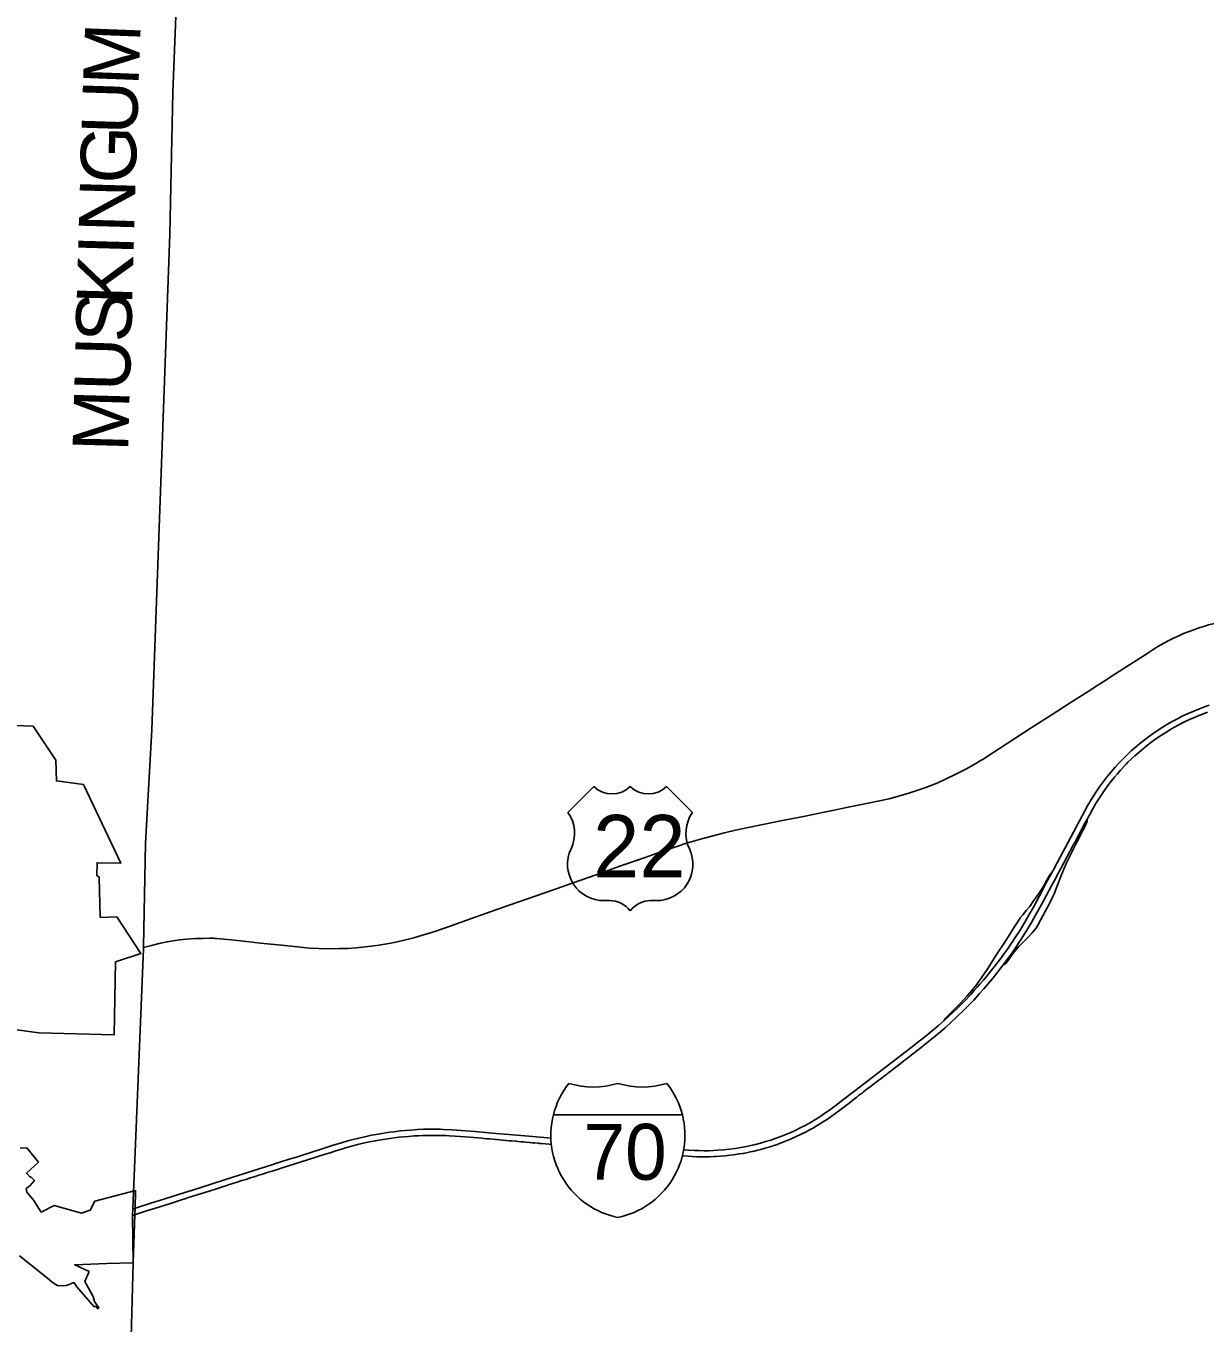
# Model space of a CAD drawing. Extents: x 1913970 to 2397567, y 78841 to 829347.
# Drawn here: x 2183521 to 2204756, y 720753 to 744108 of the extents above; entities that cross this region are included whole.
import ezdxf

# ---------------------------------------------------------------- set-up
doc = ezdxf.new("R2010")
doc.units = 0
for name, color, linetype in [('GM_X_Corporation', 7, 'Continuous'), ('GM_X_County', 7, 'Continuous'), ('GM_X_County_Text', 7, 'Continuous'), ('GM_X_Interstate_Location', 7, 'Continuous'), ('GM_X_Interstate_Shield', 7, 'Continuous'), ('GM_X_US_Location', 7, 'Continuous'), ('GM_X_US_Route', 7, 'Continuous'), ('GM_X_US_Shield', 7, 'Continuous'), ('UT_P_Electric', 7, 'Continuous')]:
    doc.layers.add(name, color=color, linetype=linetype)

msp = doc.modelspace()

# ---------------------------------------------------------------- linework, layer by layer
at = {"layer": 'GM_X_Corporation'}
for points in [[(2182981, 731524), (2183650, 731502), (2184058, 730889), (2184071, 730515), (2184559, 730451), (2185232, 729036), (2184802, 729041), (2184800, 728810), (2184842, 728783), (2184858, 728058), (2185156, 728065), (2185589, 727405), (2185132, 727255), (2185107, 725943), (2183756, 725981), (2182382, 726167)], [(2183418, 723904), (2183538, 723905), (2183746, 723650), (2183529, 723453), (2183600, 723377), (2183608, 723386), (2183673, 723319), (2183591, 723223), (2183523, 723174), (2183537, 723107), (2183663, 722957), (2183797, 722750), (2184031, 722868), (2184520, 722733), (2184678, 722787), (2184759, 722946), (2185491, 723138), (2185486, 722822), (2185483, 722707), (2185450, 721840), (2184976, 721823), (2184399, 721803), (2184659, 721681), (2184581, 721503), (2184730, 721231), (2184758, 721140), (2184836, 721025), (2184813, 721009), (2184780, 721056), (2184751, 721043), (2184436, 721405), (2184414, 721441), (2184386, 721481), (2184299, 721445), (2184245, 721431), (2184179, 721424), (2184087, 721431), (2184017, 721471), (2183848, 721612), (2183406, 721965)]]:
    msp.add_lwpolyline(points, dxfattribs=at)
at = {"layer": 'GM_X_County'}
msp.add_lwpolyline([(2195235, 695229), (2195244, 698121), (2195345, 704208), (2193259, 704276), (2191227, 704339), (2187691, 704452), (2186198, 704526), (2186181, 704528), (2186154, 704528), (2184839, 704570), (2185417, 720500), (2185450, 721840), (2185440, 722692), (2185445, 722809), (2185639, 727493), (2185641, 727535), (2185674, 729391), (2185791, 731433), (2186112, 740356), (2186166, 742913), (2186360, 747780)], dxfattribs=at)
at = {"layer": 'GM_X_Interstate_Shield'}
for p, q in [((2193020, 724503), (2195343, 724503)), ((2195343, 724503), (2193020, 724503)), ((2195343, 724503), (2193020, 724503))]:
    msp.add_line(p, q, dxfattribs=at)
for centre, start, end in [((2194483, 724133), 141.669, 165.8066), ((2193740, 726512), 253.0091, 286.9909), ((2194623, 726512), 253.0091, 286.9909), ((2193880, 724133), 14.1934, 38.331), ((2194483, 724133), 165.8066, 258.463), ((2193880, 724133), 281.537, 14.1934)]:
    msp.add_arc(centre, 1509, start, end, dxfattribs=at)
at = {"layer": 'GM_X_US_Route'}
for p, q in [((2201057, 731100), (2201348, 731287)), ((2194283, 729001), (2194670, 729137)), ((2194288, 729003), (2194670, 729137)), ((2192399, 728339), (2192556, 728393)), ((2190604, 727717), (2190763, 727767)), ((2185641, 727512), (2185711, 727532))]:
    msp.add_line(p, q, dxfattribs=at)
for points in [[(2204710, 733290), (2204753, 733303), (2204820, 733322), (2204924, 733349), (2205028, 733374), (2205113, 733392), (2205203, 733409), (2205252, 733416), (2205305, 733424), (2205391, 733435), (2205574, 733455)], [(2203802, 732869), (2203851, 732900), (2203906, 732934), (2204013, 732994), (2204106, 733044), (2204188, 733085), (2204281, 733127), (2204370, 733166), (2204451, 733199), (2204553, 733236), (2204660, 733274), (2204710, 733290)], [(2202826, 732237), (2202968, 732329), (2203067, 732392), (2203152, 732448), (2203595, 732733), (2203705, 732804), (2203751, 732834), (2203802, 732869)], [(2202001, 731710), (2202324, 731918), (2202648, 732127), (2202826, 732237)], [(2201348, 731287), (2201627, 731468), (2202001, 731710)], [(2200742, 730896), (2200951, 731031), (2201057, 731100)], [(2200448, 730728), (2200597, 730810), (2200737, 730894), (2200742, 730896)], [(2198214, 730015), (2198330, 730039), (2198688, 730113), (2198864, 730149), (2199067, 730194), (2199254, 730243), (2199402, 730286), (2199566, 730340), (2199729, 730398), (2199941, 730482), (2200081, 730545), (2200267, 730634), (2200448, 730728)], [(2198219, 730016), (2198330, 730039), (2198688, 730113), (2198864, 730149), (2199067, 730194), (2199254, 730243), (2199402, 730286), (2199566, 730340), (2199729, 730398), (2199941, 730482), (2200081, 730545), (2200267, 730634), (2200448, 730728)], [(2196099, 729579), (2196299, 729625), (2196703, 729710), (2197147, 729800), (2197556, 729882), (2197899, 729952), (2198109, 729995), (2198214, 730015), (2198219, 730016)], [(2196099, 729579), (2196299, 729625), (2196703, 729710), (2197147, 729800), (2197556, 729882), (2197899, 729952), (2198109, 729995), (2198214, 730015)], [(2194670, 729137), (2195002, 729253), (2195241, 729335), (2195420, 729392), (2195669, 729465), (2195876, 729522), (2196099, 729579)], [(2192556, 728393), (2192986, 728544), (2193359, 728676), (2193788, 728826), (2194082, 728929), (2194283, 729001), (2194288, 729003)], [(2192556, 728393), (2192986, 728544), (2193359, 728676), (2193788, 728826), (2194082, 728929), (2194283, 729001)], [(2190763, 727767), (2190901, 727811), (2191159, 727900), (2191530, 728033), (2191899, 728162), (2192204, 728269), (2192399, 728339)], [(2185711, 727532), (2185781, 727552), (2185942, 727592), (2186035, 727611), (2186063, 727616)], [(2185711, 727532), (2185781, 727552), (2185942, 727592), (2186035, 727611), (2186059, 727615)], [(2186059, 727615), (2186063, 727616), (2186172, 727634), (2186287, 727650), (2186413, 727664), (2186577, 727676), (2186707, 727679), (2186833, 727680), (2186905, 727680), (2186926, 727678)], [(2186063, 727616), (2186172, 727634), (2186287, 727650), (2186413, 727664), (2186577, 727676), (2186707, 727679), (2186833, 727680), (2186905, 727680)], [(2186905, 727680), (2187016, 727673), (2187217, 727654), (2187438, 727630)], [(2186926, 727678), (2187016, 727673), (2187217, 727654), (2187438, 727630)], [(2187438, 727630), (2187746, 727595), (2188183, 727548), (2188467, 727518), (2188627, 727504), (2188797, 727496), (2188981, 727491), (2189163, 727494), (2189319, 727499), (2189469, 727510), (2189683, 727531), (2189838, 727552), (2190023, 727581), (2190152, 727605), (2190310, 727640), (2190389, 727659), (2190508, 727690), (2190604, 727717)]]:
    msp.add_lwpolyline(points, dxfattribs=at)
at = {"layer": 'GM_X_US_Shield'}
for p, q in [((2193750, 730414), (2193283, 729947)), ((2195524, 729947), (2195057, 730414)), ((2193937, 728360), (2194030, 728360)), ((2194777, 728360), (2194871, 728360))]:
    msp.add_line(p, q, dxfattribs=at)
for centre, radius, start, end in [((2194077, 730748), 467, 225.573, 314.427), ((2194731, 730748), 467, 225.573, 314.427), ((2192747, 729572), 654, 334.5471, 35.0009), ((2196060, 729572), 654, 144.9991, 205.4529), ((2193929, 729013), 654, 154.8319, 270.6383), ((2194878, 729013), 654, 269.3617, 25.1681), ((2194030, 727893), 467, 36.8699, 90), ((2194777, 727893), 467, 90, 143.1301)]:
    msp.add_arc(centre, radius, start, end, dxfattribs=at)
at = {"layer": 'UT_P_Electric'}
for points in [[(2199566, 725655), (2199612, 725691), (2199777, 725821), (2199895, 725916), (2199990, 725995), (2200077, 726071), (2200171, 726157), (2200286, 726264), (2200402, 726376), (2200501, 726476), (2200589, 726568), (2200696, 726685), (2200772, 726770), (2200878, 726895), (2200962, 726996), (2201027, 727078), (2201121, 727200), (2201211, 727321), (2201282, 727420), (2201342, 727506), (2201434, 727645), (2201487, 727728), (2201567, 727856), (2201632, 727966), (2201705, 728095), (2201803, 728276), (2201901, 728459), (2201996, 728635), (2202042, 728722), (2202121, 728869), (2202157, 728936), (2202266, 729142), (2202380, 729355), (2202408, 729408), (2202481, 729543), (2202563, 729697), (2202633, 729824), (2202685, 729922), (2202741, 730022), (2202797, 730119), (2202842, 730192), (2202890, 730266), (2202939, 730336), (2203006, 730429), (2203072, 730515), (2203126, 730581), (2203179, 730644), (2203233, 730706), (2203249, 730723), (2203300, 730779), (2203337, 730817), (2203368, 730849), (2203427, 730907), (2203490, 730964), (2203561, 731027), (2203647, 731099), (2203683, 731128), (2203752, 731183), (2203823, 731236), (2203890, 731284), (2203969, 731337), (2204066, 731399), (2204150, 731450), (2204207, 731483), (2204282, 731524), (2204323, 731546), (2204411, 731590), (2204488, 731626), (2204563, 731659), (2204642, 731692), (2204725, 731724), (2204802, 731753)], [(2201995, 728861), (2202009, 728887), (2202024, 728914), (2202098, 729053), (2202284, 729401), (2202590, 729973), (2202647, 730077), (2202693, 730156), (2202741, 730234), (2202797, 730319), (2202856, 730406), (2202928, 730503), (2203002, 730599), (2203071, 730683), (2203144, 730767), (2203192, 730820), (2203219, 730849), (2203292, 730925), (2203360, 730991), (2203427, 731053), (2203498, 731116), (2203576, 731181), (2203661, 731249), (2203736, 731306), (2203821, 731368), (2203902, 731424), (2203985, 731477), (2204068, 731529), (2204165, 731584), (2204260, 731635), (2204357, 731684), (2204452, 731728), (2204551, 731772), (2204657, 731815), (2204746, 731849), (2204832, 731879)], [(2201121, 727200), (2201138, 727207), (2201151, 727215), (2201164, 727226), (2201172, 727235), (2201197, 727268), (2201220, 727299), (2201272, 727371), (2201327, 727441), (2201399, 727526), (2201478, 727609), (2201570, 727703), (2201644, 727778), (2201675, 727815), (2201706, 727855), (2201721, 727878), (2201751, 727930), (2201960, 728320), (2202010, 728419), (2202038, 728483), (2202088, 728610), (2202166, 728812), (2202226, 728958), (2202257, 729028), (2202293, 729102), (2202320, 729159), (2202453, 729424), (2202555, 729624), (2202594, 729701), (2202617, 729747), (2202625, 729766), (2202633, 729791), (2202635, 729804), (2202633, 729824)], [(2199479, 725726), (2199520, 725757), (2199634, 725846), (2199732, 725923), (2199811, 725988), (2199884, 726049), (2199956, 726111), (2200058, 726201), (2200069, 726211), (2200127, 726264), (2200226, 726356), (2200292, 726419), (2200355, 726481), (2200429, 726557), (2200535, 726669), (2200599, 726739), (2200659, 726805), (2200702, 726854), (2200764, 726926), (2200846, 727024), (2200935, 727134), (2201027, 727253), (2201085, 727329), (2201147, 727414), (2201196, 727484), (2201271, 727592), (2201338, 727693), (2201414, 727812), (2201469, 727902), (2201536, 728015), (2201606, 728137), (2201665, 728243), (2201823, 728538), (2201903, 728689), (2201995, 728861)], [(2201995, 728861), (2201988, 728857), (2201984, 728854), (2201981, 728851), (2201978, 728847), (2201973, 728841), (2201966, 728829), (2201956, 728813), (2201897, 728708), (2201858, 728640), (2201820, 728577), (2201774, 728503), (2201734, 728444), (2201656, 728335), (2201598, 728256), (2201536, 728179), (2201472, 728102), (2201429, 728049), (2201414, 728027), (2201333, 727902), (2201250, 727771), (2201136, 727595), (2201026, 727425), (2200922, 727262), (2200844, 727139), (2200738, 726981), (2200638, 726844), (2200554, 726742), (2200472, 726647), (2200415, 726584), (2200332, 726497), (2200274, 726435), (2200215, 726373), (2200139, 726300), (2200091, 726253), (2200081, 726242), (2200072, 726229), (2200065, 726217), (2200058, 726201)], [(2195343, 723764), (2195368, 723762), (2195446, 723757), (2195521, 723752), (2195606, 723748), (2195681, 723746), (2195701, 723746), (2195776, 723745), (2195832, 723747), (2195917, 723750), (2195953, 723752), (2196032, 723757), (2196116, 723764), (2196198, 723773), (2196266, 723782), (2196367, 723797), (2196421, 723806), (2196441, 723808), (2196466, 723814), (2196524, 723826), (2196595, 723840), (2196608, 723842), (2196633, 723849), (2196700, 723865), (2196757, 723879), (2196770, 723882), (2196798, 723890), (2196854, 723907), (2196924, 723927), (2196936, 723931), (2197014, 723957), (2197095, 723983), (2197155, 724008), (2197198, 724025), (2197292, 724064), (2197381, 724104), (2197482, 724152), (2197575, 724199), (2197659, 724244), (2197705, 724270), (2197801, 724327), (2197848, 724356), (2197898, 724388), (2197909, 724395), (2197974, 724438), (2198023, 724472), (2198047, 724489), (2198081, 724514), (2198112, 724538), (2198179, 724586), (2198248, 724640), (2198303, 724682), (2198314, 724690), (2198344, 724715), (2198380, 724744), (2198437, 724787), (2198445, 724793), (2198484, 724823), (2198515, 724848), (2198567, 724887), (2198578, 724895), (2198606, 724917), (2198647, 724950), (2198723, 725007), (2198783, 725052), (2198856, 725108), (2198921, 725158), (2198999, 725218), (2199062, 725266), (2199210, 725381), (2199295, 725447), (2199355, 725493), (2199371, 725505), (2199435, 725551), (2199488, 725594), (2199566, 725655)], [(2195367, 723873), (2195455, 723866), (2195560, 723860), (2195639, 723857), (2195738, 723855), (2195813, 723856), (2195905, 723859), (2195984, 723864), (2196088, 723872), (2196190, 723883), (2196294, 723897), (2196398, 723914), (2196498, 723933), (2196597, 723954), (2196658, 723968), (2196750, 723992), (2196842, 724019), (2196936, 724048), (2197029, 724080), (2197115, 724112), (2197207, 724149), (2197306, 724191), (2197384, 724227), (2197479, 724273), (2197566, 724319), (2197649, 724365), (2197728, 724412), (2197817, 724468), (2197910, 724530), (2197991, 724587), (2198091, 724661), (2198253, 724785), (2198552, 725014), (2198815, 725216), (2199379, 725650), (2199463, 725713), (2199479, 725726)], [(2185446, 722806), (2185513, 722826), (2185786, 722915), (2185926, 722959), (2186367, 723099), (2186614, 723176), (2186895, 723266), (2187230, 723373), (2187967, 723608), (2188036, 723630), (2188054, 723637), (2188062, 723639), (2188095, 723649), (2188261, 723702), (2188349, 723729), (2188427, 723752), (2188874, 723896), (2189033, 723947), (2189221, 724005), (2189335, 724037), (2189490, 724078), (2189624, 724109), (2189743, 724134), (2189830, 724150), (2189936, 724169), (2190066, 724188), (2190144, 724199), (2190265, 724213), (2190359, 724221), (2190451, 724229), (2190568, 724237), (2190680, 724242), (2190840, 724244), (2190978, 724243), (2191043, 724241), (2191188, 724235), (2191361, 724223), (2191612, 724201), (2191982, 724169), (2192063, 724162), (2192220, 724148), (2192580, 724116), (2192916, 724088), (2192975, 724083)], [(2185442, 722689), (2185675, 722766), (2185913, 722842), (2186141, 722914), (2186217, 722937), (2186307, 722966), (2186385, 722991), (2186451, 723012), (2186529, 723036), (2186620, 723065), (2186726, 723099), (2186854, 723140), (2186932, 723165), (2187045, 723201), (2187138, 723232), (2187163, 723240), (2187248, 723266), (2187326, 723290), (2187411, 723317), (2187480, 723339), (2187564, 723365), (2187649, 723392), (2187717, 723413), (2187799, 723439), (2187886, 723467), (2187958, 723490), (2188087, 723531), (2188118, 723541), (2188346, 723613), (2188743, 723738), (2188909, 723791), (2188999, 723820), (2189084, 723847), (2189162, 723871), (2189241, 723895), (2189320, 723917), (2189411, 723943), (2189494, 723965), (2189570, 723984), (2189650, 724002), (2189737, 724020), (2189814, 724035), (2189879, 724047), (2189999, 724066), (2190077, 724077), (2190152, 724087), (2190237, 724097), (2190322, 724106), (2190410, 724114), (2190515, 724122), (2190587, 724126), (2190669, 724130), (2190747, 724132), (2190833, 724133), (2190915, 724133), (2190984, 724132), (2191010, 724131), (2191085, 724129), (2191144, 724126), (2191249, 724120), (2191341, 724114), (2191429, 724107), (2191508, 724100), (2191589, 724093), (2191674, 724085), (2191733, 724080), (2191815, 724072), (2191844, 724070), (2191873, 724067), (2191936, 724062), (2191984, 724057), (2192007, 724055), (2192105, 724045), (2192226, 724035), (2192268, 724031), (2192340, 724026), (2192347, 724025), (2192386, 724021), (2192435, 724017), (2192484, 724013), (2192520, 724010), (2192585, 724004), (2192601, 724003), (2192637, 724000), (2192683, 723997), (2192754, 723989), (2192770, 723988), (2192797, 723986), (2192872, 723979), (2192944, 723972), (2192983, 723968)]]:
    msp.add_lwpolyline(points, dxfattribs=at)

# ---------------------------------------------------------------- texts
at = {"layer": 'GM_X_County_Text'}
for s, rotation, p in [('M', 87.8244, (2185547, 743024)), ('U', 88.175, (2185519, 742141)), ('G', 88.3839, (2185494, 741258)), ('N', 88.4037, (2185469, 740374)), ('I', 88.4017, (2185458, 739965)), ('K', 88.4035, (2185433, 739081)), ('S', 88.4017, (2185414, 738404)), ('U', 88.4037, (2185390, 737520)), ('M', 88.4017, (2185359, 736433))]:
    msp.add_text(s, height=1000, rotation=rotation, dxfattribs=at).set_placement(p)
at = {"layer": 'GM_X_Interstate_Location'}
for s in ['.', '-', ',']:
    msp.add_text(s, height=1, dxfattribs=at).set_placement((2193947, 723890))
msp.add_text('70', height=1, rotation=0, dxfattribs=at).set_placement((2193743, 723683))
at = {"layer": 'GM_X_Interstate_Shield'}
msp.add_text('70', height=1006.2, dxfattribs=at).set_placement((2193563, 723333))
at = {"layer": 'GM_X_US_Location'}
for s, p in [('0', (2194226, 728963)), ('/', (2194227, 728963))]:
    msp.add_text(s, height=1, dxfattribs=at).set_placement(p)
msp.add_text('22', height=1, rotation=0, dxfattribs=at).set_placement((2194020, 728756))
at = {"layer": 'GM_X_US_Shield'}
msp.add_text('22', height=1120.7, dxfattribs=at).set_placement((2193734, 728780))

doc.saveas('drawing.dxf')
